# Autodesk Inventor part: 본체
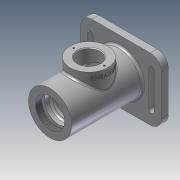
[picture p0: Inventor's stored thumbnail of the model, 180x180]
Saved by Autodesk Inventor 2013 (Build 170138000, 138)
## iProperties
Created: 2021-07
Part Number: 본체
Material: 알루미늄 6061
Document SubType Name: Modeling
Designer: 19
Density: 2.71 g/cm^3
Mass: 742.646 g
Surface Area: 651.172 cm^2
Volume: 274.039 cm^3
Author: 19
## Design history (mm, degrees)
sketch "스케치1"
  geometry: L1 (-57.5, 0)-(57.5, 0); L2 (-57.5, 0)-(-57.5, 31); L3 (-57.5, 31)-(57.5, 31); L4 (57.5, 31)-(57.5, 0); L5 (-57.5, 21)-(-48.5, 21); L6 (-48.5, 21)-(-48.5, 24); L7 (-48.5, 24)-(-45.5, 24); L8 (-45.5, 24)-(-45.5, 20); L9 (-45.5, 20)-(-36.5, 20); L10 (-36.5, 20)-(-36.5, 17.5); L11 (-36.5, 17.5)-(-33.25, 17.5); L12 (-33.25, 17.5)-(-33.25, 18.5); L13 (-33.25, 18.5)-(-31.5, 18.5); L14 (-31.5, 18.5)-(-31.5, 17.5); L15 (-31.5, 17.5)-(-20.5, 17.5); L16 (-20.5, 17.5)-(-20.5, 26); L17 (-20.5, 26)-(17.5, 26); L18 (17.5, 26)-(17.5, 17.5); L19 (17.5, 17.5)-(28.5, 17.5); L20 (28.5, 17.5)-(28.5, 16); L21 (28.5, 16)-(33.5, 16); L22 (33.5, 16)-(33.5, 10); L23 (33.5, 10)-(36.2, 10); L24 (36.2, 10)-(36.2, 12.5); L25 (36.2, 12.5)-(43.5, 12.5); L26 (43.5, 12.5)-(57.5, 22); 2 further points
  constraints: 52 end point, 12 parallel, 12 perpendicular, 2 point on line, 1 coincident, 1 horizontal, 1 midpoint
  dimensions: "d0" = 115 distance of L1.start L1.end; "d1" = 62 diameter of L3 L1; "d2" = 9 distance of L5.start L5.end; "d3" = 3 distance of L6.end L7.end; "d4" = 9 distance of L8.end L9.end; "d5" = 38 distance of L16.end L17.end; "d6" = 11 distance of L14.end L15.end; "d7" = 11 distance of L18.end L19.end; "d8" = 1.75 distance of L12.end L13.end; "d9" = 65 distance of L19.end L10.end; "d10" = 91 horizontal distance of L21.end L5.start; "d11" = 14 horizontal distance of L25.end L26.end; "d12" = 7.3 distance of L24.end L25.end; "d13" = 42 diameter of L5 L1; "d14" = 40 diameter of L9 L1; "d15" = 48 diameter of L7 L1; "d16" = 35 diameter of L15 L1; "d17" = 35 diameter of L11 L1; "d18" = 37 diameter of L13 L1; "d19" = 52 diameter of L17 L1; "d20" = 35 diameter of L19 L1; "d21" = 32 diameter of L21 L1; "d22" = 20 diameter of L23 L1; "d23" = 25 diameter of L25 L1; "d24" = 44 diameter of L26.end L1
revolve "회전1" sketch "스케치1" stored, may be unused: angle "d25" = 90 deg
node "작업 평면1"
sketch "스케치2"
  geometry: L1 (-58, 45)-(58, 45); L2 (58, 45)-(58, -45); L3 (58, -45)-(-58, -45); L4 (-58, -45)-(-58, 45); L5 (-58, 45)-(58, -45); L6 (58, 45)-(-58, -45); C1 r 31 at (0, 0) reference; 1 further point
  constraints: 12 end point, 2 midpoint, 2 parallel, 1 horizontal, 1 perpendicular
  dimensions: "d27" = 116 distance of L2.end L3.end; "d28" = 90 distance of L1.end L2.end
extrude "돌출1" join sketch "스케치2" distance "d29" = 10; taper "d30" = 0 deg
sketch "스케치3"
  geometry: C1 r 31 at (0, 0) reference; C2 r 35 at (0, 0)
  constraints: 1 centre point, 1 coincident
  dimensions: "d31" = 70 diameter of C2
extrude "돌출2" join sketch "스케치3" stored distance "d32" = 10; taper "d33" = 0 deg
fillet "모깎기1" dims "d34" = 16
sketch "스케치4"
  geometry: L1 (40, 25)-(40, -25); L2 (48, -25)-(48, 25); C1 r 35 at (0, 0) reference; A1 r 4 centre (44, 25) between (40, 25) and (48, 25); A2 r 4 centre (44, -25) between (40, -25) and (48, -25)
  constraints: 4 end point, 4 point on circle, 3 tangent, 2 centre point, 1 parallel
  dimensions: "d35" = 8 diameter of A1; "d36" = 8 diameter of A2; "d37" = 50 distance of A2.centre A1.centre; "d38" = 44 horizontal distance of C1.centre A1.centre; "d39" = 25 vertical distance of A1.centre C1.centre; "d40" = 25 vertical distance of C1.centre A2.centre
extrude "돌출3" cut sketch "스케치4" stored distance "d41" = 10; taper "d42" = 0 deg
node "작업 평면2"
sketch "스케치5"
  geometry: L1 (57.5, 31)-(57.5, -31) reference; L2 (57.5, 31)-(-44.5, 31) reference; C1 r 27 at (1.5, 0); 1 further point
  constraints: 1 centre point, 1 coincident
  dimensions: "d44" = 54 diameter of C1; "d81" = 56 distance from line of L1 point (1.5, 0); "d82" = 31 distance from line of L2 point (1.5, 0)
extrude "돌출4" join sketch "스케치5" stored distance "d45" = 10; taper "d46" = 0 deg
sketch "스케치6"
  geometry: C1 r 27 at (0, 0) reference; C2 r 16 at (0, 0)
  constraints: 1 centre point, 1 coincident
  dimensions: "d47" = 32 diameter of C2
extrude "돌출5" cut sketch "스케치6" stored distance "d49" = 10; taper "d50" = 0 deg
sketch "스케치7"
  geometry: L1 (0, 0)-(0, 22); L2 (0, 0)-(0, -22); C1 r 27 at (0, 0) reference; 2 further points
  constraints: 4 end point, 2 coincident, 1 collinear, 1 vertical
  dimensions: "d51" = 22 distance of L1.start L1.end; "d52" = 22 distance of L1.start L2.end
hole "구멍1" sketch "스케치7" at (0, 22), (0, -22) diameter "d53" = 2.459; stored, may be unused: countersink angle "d57" = 90 deg, drill point angle "d59" = 118 deg; dims "d54" = 6, "d55" = 4, "d56" = 2, "d58" = 8
fillet "모깎기2" dims "d60" = 3
feature "스레드1" dims "d61" = 10, "d62" = 0
node "작업 평면3"
sketch "스케치8"
  geometry: L1 (-28.5, 42)-(25.5, 42) reference; 2 further points
  constraints: 1 vertical alignment, 1 other
  dimensions: "d64" = 8 distance from line of L1 point (0, 34)
feature "엠보싱1" sketch "스케치8" dims "d4" = 9, "d65" = 0.5, "d66" = 0
chamfer "모따기1" distance "d67" = 1; stored, may be unused: second distance "d68" = 2, angle "d69" = 45 deg
fillet "모깎기3" dims "d70" = 0.3
fillet "모깎기4" dims "d71" = 0.3
chamfer "모따기3" distance "d76" = 0.7; stored, may be unused: second distance "d77" = 2, angle "d78" = 45 deg
fillet "모깎기6" dims "d79" = 3
fillet "모깎기7" dims "d80" = 3
node "솔리드1"
mirror "대칭1"
other parameters: "d26" = -3, "d43" = 42
